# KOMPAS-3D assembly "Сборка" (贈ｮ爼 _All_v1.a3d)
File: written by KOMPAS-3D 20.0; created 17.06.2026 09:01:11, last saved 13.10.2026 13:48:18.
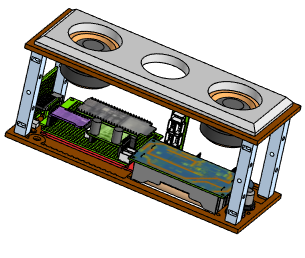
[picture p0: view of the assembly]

Document properties: Полное имя файла: D:\RicWork\Project-EPS32\box_compas\Сборка_All_v1.a3d

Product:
- Part/product: Сборка
    Масса: 2.30929
  - Component [assembly]: Сборка  | Масса: 0.825473; source file: Back_Panel_Сборка_v2.a3d
  - Component [assembly]: Сборка  | Масса: 0.290983; source file: Back_Panel_Сборка_v1.a3d
  - Component [assembly]: Сборка  | Масса: 0.106673; source file: boxСборка.a3d
  - Component [assembly]: Сборка  | Масса: 0.875289; source file: Front_Panel_Сборка_v2.a3d
  - Component [detail]: Деталь  | qty 4  | Масса: 0.0527189; source file: Panel_стяжка.m3d

Referenced files in D:\RicWork\Project-EPS32\box_compas\: boxСборка.a3d, Front_Panel_Сборка_v2.a3d, Back_Panel_Сборка_v1.a3d, Panel_стяжка.m3d, Back_Panel_Сборка_v2.a3d
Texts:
  Деталь (1)
  Деталь (2)
  Деталь (3)
  Деталь (4)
